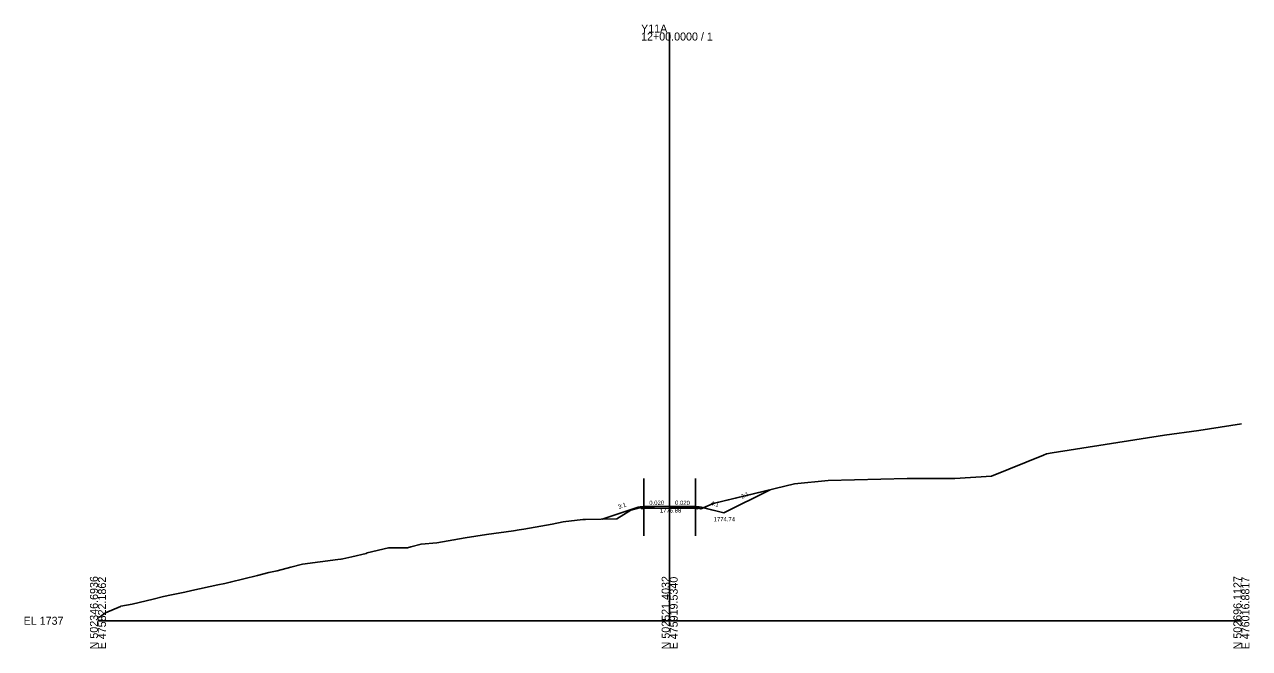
# Model space of a CAD drawing. Extents: x -26 to 403, y -10 to 5098.
# Drawn here: x -25.7 to 402.8, y 1990.3 to 2208.4 of the extents above; entities that cross this region are included whole.
import ezdxf

# ---------------------------------------------------------------- set-up
doc = ezdxf.new("R2010")
doc.units = 0
for name, color, linetype in [('Exist Cross Section Cell', 7, 'Continuous'), ('Exist XS Center Line Elevation Label', 7, 'Continuous'), ('Exist XS Ground Line', 7, 'Continuous'), ('Prop XS Ditch Slope Text', 7, 'Continuous'), ('Prop XS Ditch Standard Text', 7, 'Continuous'), ('Prop XS Dump Level', 7, 'Continuous'), ('Prop XS Earthwork Shape', 7, 'Continuous'), ('Prop XS EOT Tick Mark', 7, 'Continuous'), ('Prop XS Finish Grade', 7, 'Continuous'), ('Prop XS Finish Grade Earthwork', 7, 'Continuous'), ('Prop XS Finish Grade Pavement', 7, 'Continuous'), ('Prop XS Hydro Fill Slope Data', 7, 'Continuous'), ('Prop XS Hydro Typical Ditch Data', 7, 'Continuous'), ('Prop XS Pvmt Edge Slope', 7, 'Continuous'), ('Prop XS SE Text', 7, 'Continuous'), ('Prop XS Shoulder Borrow Shape', 7, 'Continuous'), ('Prop XS Side Slope Text', 7, 'Continuous'), ('Prop XS Subgrade Earthwork', 7, 'Continuous'), ('Scratch_Level_5', 7, 'Continuous')]:
    doc.layers.add(name, color=color, linetype=linetype)

msp = doc.modelspace()

# ---------------------------------------------------------------- linework, layer by layer
at = {"layer": 'Exist Cross Section Cell'}
for p, q in [((200, 2000), (200, 2205.65)), ((0, 2000), (200, 2000)), ((200, 2000), (400, 2000))]:
    msp.add_line(p, q, dxfattribs=at)
at = {"layer": 'Exist XS Ground Line'}
msp.add_lwpolyline([(0, 2001.42), (0.53, 2001.29), (2.61, 2002.82), (7.93, 2004.96), (7.99, 2005.08), (11.94, 2005.85), (19.37, 2007.59), (22.99, 2008.43), (25.74, 2009.02), (30.34, 2010), (32.9, 2010.58), (41.92, 2012.51), (44.35, 2013.02), (46.29, 2013.48), (55.8, 2015.86), (59.75, 2016.88), (62.75, 2017.45), (67.46, 2018.76), (71.55, 2019.76), (83.95, 2021.36), (84.97, 2021.51), (85.65, 2021.64), (88.77, 2022.35), (93.8, 2023.56), (94.23, 2023.75), (101.6, 2025.48), (107.04, 2025.53), (108.27, 2025.52), (109.4, 2025.83), (113.05, 2026.8), (118.57, 2027.26), (124.5, 2028.26), (128.48, 2028.95), (135.95, 2030.14), (145.35, 2031.49), (147.4, 2031.81), (149.03, 2032.06), (158.85, 2033.72), (162.69, 2034.54), (169.58, 2035.35), (170.01, 2035.4), (170.56, 2035.42), (181.49, 2035.63), (186.4, 2038.68), (190.46, 2039.67), (199.02, 2039.91), (199.46, 2039.89), (200, 2039.88), (209.09, 2039.71), (209.75, 2039.45), (210.96, 2039.09), (213.39, 2040.2), (214.99, 2040.93), (215.7, 2041.12), (243.68, 2047.88), (255.42, 2049.05), (283.04, 2049.73), (299.78, 2049.79), (312.58, 2050.55), (330.81, 2057.93), (331.82, 2058.34), (333.8, 2058.66), (373.16, 2064.85), (385.1, 2066.53), (400, 2068.88)], dxfattribs=at)
at = {"layer": 'Prop XS Dump Level'}
msp.add_line((200, 2040.08), (209, 2039.9), dxfattribs=at)
at = {"layer": 'Prop XS Earthwork Shape'}
for points in [[(211.89, 2039.52), (213.39, 2040.2), (214.99, 2040.93), (215.7, 2041.12), (235.15, 2045.81), (219, 2037.74)], [(189.91, 2039.54), (190.46, 2039.67), (199.02, 2039.91), (199.46, 2039.89), (200, 2039.88), (209.09, 2039.71), (209.75, 2039.45), (209.94, 2039.39), (209.72, 2039.18), (209, 2039.19), (200, 2039.37), (191, 2039.19), (190.28, 2039.18)], [(189.91, 2039.54), (189.66, 2039.79), (189, 2039.74), (176.37, 2035.53), (181.49, 2035.63), (186.4, 2038.68)], [(209.94, 2039.39), (210.34, 2039.79), (211, 2039.74), (211.89, 2039.52), (210.96, 2039.09)]]:
    msp.add_lwpolyline(points, close=True, dxfattribs=at)
at = {"layer": 'Prop XS EOT Tick Mark'}
for p, q in [((191, 2039.9), (191, 2040.9)), ((209, 2039.9), (209, 2040.9))]:
    msp.add_line(p, q, dxfattribs=at)
at = {"layer": 'Prop XS Finish Grade'}
for p, q in [((191, 2039.9), (189.66, 2039.79)), ((209, 2039.9), (210.34, 2039.79))]:
    msp.add_line(p, q, dxfattribs=at)
at = {"layer": 'Prop XS Finish Grade Earthwork'}
for p, q in [((219, 2037.74), (235.15, 2045.81)), ((189, 2039.74), (176.37, 2035.53)), ((189.66, 2039.79), (189, 2039.74)), ((210.34, 2039.79), (211, 2039.74)), ((211, 2039.74), (219, 2037.74))]:
    msp.add_line(p, q, dxfattribs=at)
at = {"layer": 'Prop XS Finish Grade Pavement'}
for p, q in [((191, 2039.9), (200, 2040.08)), ((200, 2040.08), (209, 2039.9))]:
    msp.add_line(p, q, dxfattribs=at)
at = {"layer": 'Prop XS Hydro Fill Slope Data'}
msp.add_line((189, 2039.74), (176.37, 2035.53), dxfattribs=at)
at = {"layer": 'Prop XS Hydro Typical Ditch Data'}
for p, q in [((219, 2037.74), (235.15, 2045.81)), ((211, 2039.74), (219, 2037.74))]:
    msp.add_line(p, q, dxfattribs=at)
at = {"layer": 'Prop XS Pvmt Edge Slope'}
for p, q in [((191, 2039.9), (190.28, 2039.18)), ((209, 2039.9), (209.72, 2039.18))]:
    msp.add_line(p, q, dxfattribs=at)
at = {"layer": 'Prop XS Shoulder Borrow Shape'}
for points in [[(191, 2039.9), (189.66, 2039.79), (190.28, 2039.18)], [(209, 2039.9), (210.34, 2039.79), (209.72, 2039.18)]]:
    msp.add_lwpolyline(points, close=True, dxfattribs=at)
at = {"layer": 'Prop XS Subgrade Earthwork'}
for p, q in [((190.28, 2039.18), (189.66, 2039.79)), ((191, 2039.19), (190.28, 2039.18)), ((200, 2039.37), (191, 2039.19)), ((209, 2039.19), (200, 2039.37)), ((209, 2039.19), (209.72, 2039.18)), ((209.72, 2039.18), (210.34, 2039.79))]:
    msp.add_line(p, q, dxfattribs=at)
at = {"layer": 'Scratch_Level_5'}
for p, q in [((191, 2049.69), (191, 2029.69)), ((209, 2049.71), (209, 2029.71))]:
    msp.add_line(p, q, dxfattribs=at)

# ---------------------------------------------------------------- texts
at = {"layer": 'Exist Cross Section Cell'}
for s, p in [('Y11A', (190, 2205.65)), ('12+00.0000 / 1', (190, 2202.85)), ('EL 1737', (-26, 1998.6))]:
    msp.add_text(s, height=2.8, dxfattribs=at).set_placement(p)
for s, p in [('N 502346.6936', (0, 1990)), ('E 475822.1862', (2.8, 1990)), ('N 502521.4032', (200, 1990)), ('E 475919.5340', (202.8, 1990)), ('N 502696.1127', (400, 1990)), ('E 476016.8817', (402.8, 1990))]:
    msp.add_text(s, height=2.8, rotation=90, dxfattribs=at).set_placement(p)
at = {"layer": 'Exist XS Center Line Elevation Label'}
msp.add_text('1776.88', height=1.5, dxfattribs=at).set_placement((196.58, 2037.83))
at = {"layer": 'Prop XS Ditch Slope Text'}
msp.add_text('4:1', height=1.5, rotation=345.9638, dxfattribs=at).set_placement((214.21, 2040.48))
at = {"layer": 'Prop XS Ditch Standard Text'}
msp.add_text('1774.74', height=1.5, dxfattribs=at).set_placement((215.38, 2034.74))
at = {"layer": 'Prop XS Dump Level'}
for p in [(189, 2039.7), (211, 2039.7)]:
    msp.add_text('Case1', height=0.04, dxfattribs=at).set_placement(p)
at = {"layer": 'Prop XS SE Text'}
for rotation, p in [(1.1458, (192.88, 2040.44)), (358.8542, (201.88, 2040.54))]:
    msp.add_text('0.020', height=1.5, rotation=rotation, dxfattribs=at).set_placement(p)
at = {"layer": 'Prop XS Side Slope Text'}
for s, rotation, p in [('2:1', 26.5651, (225.34, 2042.59)), ('3:1', 18.4349, (182.21, 2039.06))]:
    msp.add_text(s, height=1.5, rotation=rotation, dxfattribs=at).set_placement(p)

doc.saveas('drawing.dxf')
